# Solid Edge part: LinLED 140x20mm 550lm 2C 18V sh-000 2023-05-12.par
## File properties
Author: jaroslaw.przewlocki
Template: iso metric part.par
Last saved by: jaroslaw.przewlocki
Revision: 1
Application: Solid Edge
Gęstość: 0,000 kg/m^3
Dokładność: 0,990
Username: jaroslaw.przewlocki
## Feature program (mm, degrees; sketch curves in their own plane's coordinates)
body "unnamed Body 1"
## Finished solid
Body 1: solid body, 806 faces, 2074 edges, 1324 vertices.
  Faces by surface: plane 504, cylinder 146, torus 64, cone 50, spline 26, sphere 16
  Edges by curve: line 1434, curve on surface 356, circle 182, ellipse 66, spline 36
Bounding box of the edges (mm; curved faces can reach further): 139.600 x 20.000 x 4.450, from (-69.8, -10, -1) to (69.8, 10, 3.45).
Cylindrical faces by radius (mm): R0.2 x46, R0.2169 x6, R0.25 x20, R0.3373 x6, R0.4 x8, R0.4006 x2, R0.4008 x2, R0.525 x2, R0.6 x20, R1 x12, R1.1 x4, R1.1989 x2, R1.199 x2, R1.2 x10, R2.15 x4
Conical faces (half-angle, radius in mm at the cone's reference point): 0.398 deg R1.1964 x2, 0.4493 deg R1.1964 x2, 0.4746 deg R1.1948 x2, 0.4758 deg R1.1948 x2, 0.5 deg R0.5056 x4, 0.5 deg R1.0082 x4, 1 deg R0.5511 x2, 10 deg R0.2132 x4, 10 deg R0.4132 x4, 16.0099 deg R1.1053 x2, 16.1249 deg R1.1279 x2, 18.8604 deg R1.0669 x4, 19.5041 deg R0.5138 x2, 19.8244 deg R0.5099 x2, 27.363 deg R0.6214 x2, 40.6434 deg R0.5161 x2, 43.3309 deg R0.4892 x2, 45 deg R0.575 x2, 45 deg R0.625 x4
Toroidal faces (ring radius, tube radius in mm): R0.0958 r0.3997 x4, R0.1076 r0.4 x2, R0.1101 r0.4001 x2, R0.1217 r0.4 x2, R0.1234 r0.4 x2, R0.1626 r0.228 x2, R0.1634 r0.2287 x2, R0.3287 r0.2001 x2, R0.3684 r0.2151 x2, R0.3703 r0.4 x2, R0.3818 r0.2 x4, R0.4166 r0.3983 x2, R0.5981 r0.197 x2, R0.5982 r0.197 x2, R0.6009 r0.3968 x2, R0.6009 r0.3969 x2, R0.6227 r0.2 x2, R0.6235 r0.2 x2, R0.8 r0.2 x4, R0.8522 r0.3 x2, R0.9002 r0.2 x2, R0.9018 r0.2 x2, R0.9197 r0.223 x2, R0.9365 r0.2 x2, R0.9663 r0.2263 x2, R0.9665 r0.2263 x2, R1.429 r1.2 x2, R1.8741 r0.2175 x2, R1.9007 r0.2 x2
Spherical faces by radius (mm): R0.2 x12, R0.6 x4
Planar faces by outward normal: +x 56, +y 59, +z 79, -x 56, -y 59, -z 9, oblique 186
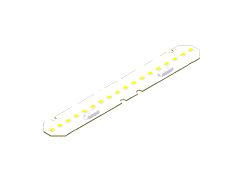
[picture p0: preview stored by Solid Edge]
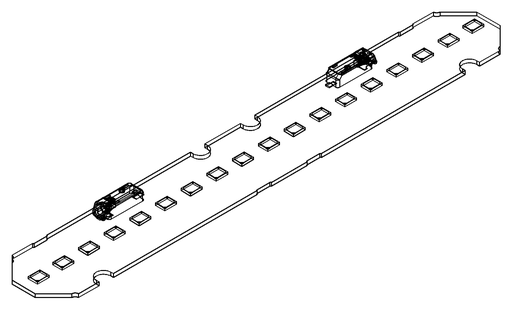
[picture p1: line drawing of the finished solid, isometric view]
